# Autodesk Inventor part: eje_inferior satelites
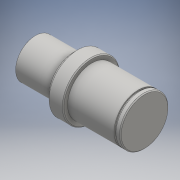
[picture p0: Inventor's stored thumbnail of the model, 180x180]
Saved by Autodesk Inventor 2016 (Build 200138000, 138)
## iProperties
Created: 2016-10
Part Number: eje_inferior satelites
Material: Generic
Document SubType Name: Modeling
Designer: Ingenieria
Density: 1 g/cm^3
Appearance: Default
Author: Ingenieria
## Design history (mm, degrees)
sketch "Sketch1"
  geometry: C1 r 32.5 at (0, 0); 1 further point
  constraints: 1 centre point, 1 coincident
  dimensions: "d0" = 65 diameter of C1
extrude "Extrusion1" new body sketch "Sketch1" stored distance "d1" = 124; taper "d2" = 0 deg
sketch "Sketch2"
  geometry: C1 r 22.5 at (0, 0); C2 r 32.5 at (0, 0); 1 further point
  constraints: 2 centre point, 2 coincident
  dimensions: "d3" = 45 diameter of C1; "d4" = 65 diameter of C2
extrude "Extrusion2" cut sketch "Sketch2" distance "d5" = 44; taper "d6" = 0 deg
sketch "Sketch3"
  geometry: C1 r 27.5 at (0, 0); C2 r 32.5 at (0, 0); 1 further point
  constraints: 2 centre point, 2 coincident
  dimensions: "d7" = 55 diameter of C1; "d8" = 65 diameter of C2
extrude "Extrusion3" cut sketch "Sketch3" distance "d9" = 60; taper "d10" = 0 deg
workplane "Work Plane1"
sketch "Sketch4"
  geometry: C1 r 26 at (0, 0); C2 r 27.5 at (0, 0); 1 further point
  constraints: 2 centre point, 2 coincident
  dimensions: "d12" = 52 diameter of C1; "d13" = 55 diameter of C2
extrude "Extrusion4" cut sketch "Sketch4" distance "d14" = 2.15; taper "d15" = 0 deg
chamfer "Chamfer1" distance "d16" = 1; stored, may be unused: second distance "d17" = 2, angle "d18" = 45 deg
chamfer "Chamfer2" distance "d19" = 1; stored, may be unused: second distance "d20" = 2, angle "d21" = 45 deg
chamfer "Chamfer3" distance "d22" = 4; stored, may be unused: second distance "d23" = 2, angle "d24" = 45 deg
body "Solid1"
other parameters: "d11" = 55
